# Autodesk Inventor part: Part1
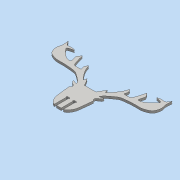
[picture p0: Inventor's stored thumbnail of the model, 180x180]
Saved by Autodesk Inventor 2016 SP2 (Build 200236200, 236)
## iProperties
Created: 2017-07
Part Number: Part1
Material: Generic
Document SubType Name: Modeling
Designer: Mohamed A.
Density: 1 g/cm^3
Appearance: Default
Author: Mohamed A.
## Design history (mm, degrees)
sketch "Sketch1"
  geometry: L1 (0, 160.105)-(0, -48.928); L2 (-179.556, 205.459)-(176.88, 205.459) reference; L3 (176.88, 205.459)-(176.88, -298.725) reference; L4 (176.88, -298.725)-(-179.556, -298.725); L5 (-179.556, -298.725)-(-179.556, 205.459) reference; L6 (1, -2.44)-(11.38, -2.44); L7 (11.38, -2.44)-(11.38, 57.095); L8 (11.38, 63.095)-(22.38, 63.095); L9 (22.38, -2.44)-(34.794, -0.274); L10 (34.794, -0.274)-(50.816, 25.275); L11 (50.816, 25.275)-(53.27, 35.957); L12 (53.27, 35.957)-(58.034, 80.417); L13 (58.034, 80.417)-(61.354, 111.74); L14 (61.354, 111.74)-(60.343, 111.74); L15 (60.343, 111.74)-(54.241, 111.74); L16 (54.241, 111.74)-(54.241, 125.454); L17 (54.241, 125.454)-(55.684, 126.32); L18 (55.684, 126.32)-(72.429, 137.29); L19 (72.429, 137.29)-(75.316, 140.755); L20 (75.316, 140.755)-(78.347, 148.983); L21 (78.347, 148.983)-(74.305, 146.673); L22 (74.305, 146.673)-(57.272, 141.476); L23 (57.272, 141.476)-(55.54, 141.476); L24 (55.54, 141.476)-(59.726, 151.003); L25 (59.726, 151.003)-(73.584, 165.438); L26 (73.584, 165.438)-(108.66, 189.689); L27 (108.66, 189.689)-(114.001, 193.009); L28 (114.001, 193.009)-(175.76, 198.946); L29 (175.76, 198.946)-(199.066, 197.096); L30 (199.066, 197.096)-(219.36, 197.096); L31 (219.36, 197.096)-(247.431, 208.846); L32 (247.431, 208.846)-(257.021, 217.738); L33 (257.021, 217.738)-(264.344, 238.835); L34 (264.344, 238.835)-(264.344, 254.353); L35 (264.344, 254.353)-(259.636, 269.696); L36 (259.636, 269.696)-(258.416, 269.696); L37 (258.416, 269.696)-(260.857, 309.408); L38 (260.857, 309.408)-(260.857, 304.741); L39 (260.857, 304.741)-(250.744, 287.828); L40 (250.744, 287.828)-(245.688, 283.295); L41 (245.688, 283.295)-(227.032, 286.782); L42 (227.032, 286.782)-(219.883, 286.782); L43 (219.883, 286.782)-(204.366, 281.9); L44 (204.366, 281.9)-(204.366, 281.552); L45 (204.366, 281.552)-(236.97, 275.479); L46 (236.97, 275.479)-(236.97, 268.301); L47 (236.97, 268.301)-(228.601, 259.932); L48 (228.601, 259.932)-(201.576, 232.907); L49 (201.576, 232.907)-(189.546, 226.456); L50 (189.546, 226.456)-(170.716, 223.666); L51 (170.716, 223.666)-(168.449, 223.666); L52 (168.449, 223.666)-(168.449, 237.266); L53 (168.449, 237.266)-(175.598, 253.655); L54 (175.598, 253.655)-(175.598, 259.06); L55 (175.598, 259.06)-(161.475, 277.542); L56 (161.475, 277.542)-(161.475, 278.588); L57 (161.475, 278.588)-(155.721, 249.819); L58 (155.721, 249.819)-(145.609, 223.143); L59 (145.609, 223.143)-(142.33, 214.494); L60 (142.33, 214.494)-(125.558, 215.123); L61 (125.558, 215.123)-(106.903, 215.123); L62 (106.903, 215.123)-(106.903, 215.472); L63 (106.903, 215.472)-(111.436, 231.861); L64 (111.436, 231.861)-(111.436, 237.44)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; A1 r 3 centre (11.38, 60.095) between (11.38, 63.095) and (11.38, 57.095); A2 r 3 centre (22.38, 60.095) between (22.38, 57.095) and (22.38, 63.095); A3 r 3 centre (-22.38, 60.095) between (-22.38, 63.095) and (-22.38, 57.095); A4 r 3 centre (-11.38, 60.095) between (-11.38, 57.095) and (-11.38, 63.095); 3 further points; 1 other entity
  constraints: 74 symmetric about line, 18 end point, 11 parallel, 8 point on circle, 7 horizontal, 7 perpendicular, 7 point on line, 4 centre point, 4 vertical, 1 tangent, 15 other
  dimensions: "d85" = 311.848 vertical distance of L37.end L6.start; "d94" = 259.85651 horizontal distance of L37.end L6.start; "d115" = 11 distance between parallel lines of L7 L76; "d116" = 65.53432 distance from line of L9.start L8; "d117" = 91.0046 distance from line of L8.end L75; "d118" = 11 distance of A3.centre A4.centre; "d119" = 3 distance of L7.end A1.centre; "d122" = 11 distance of L8.start L8.end; "d123" = 11 distance of L145.start L145.end (derived); "d124" = 3 radius of A3
extrude "Extrusion1" new body sketch "Sketch1" distance "d0" = 11; taper "d1" = 0 deg
body "Solid1"
node "Image3"
